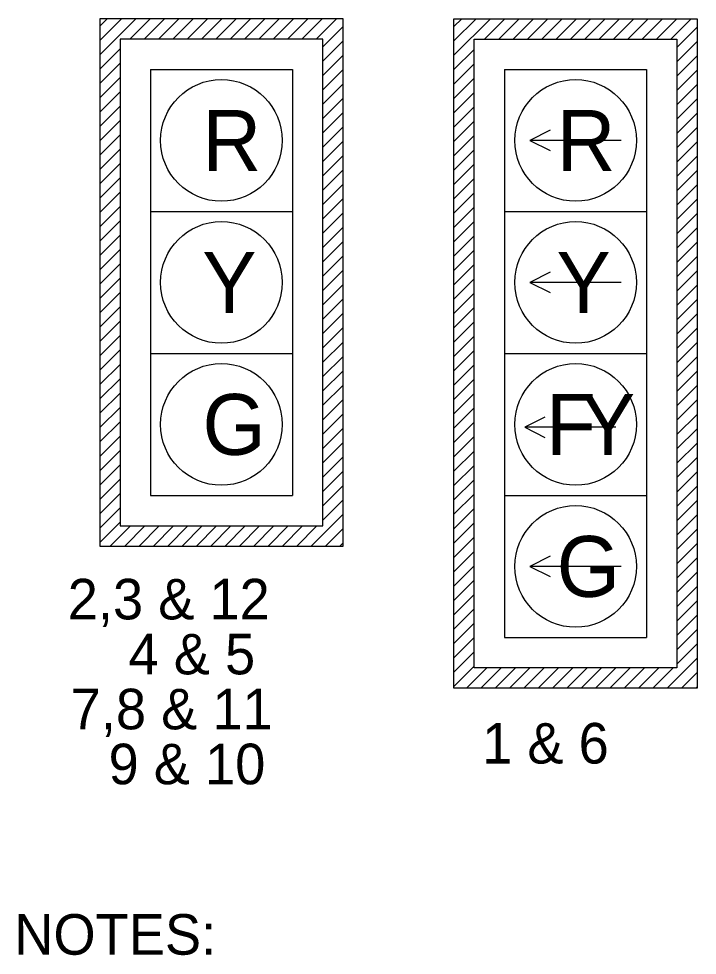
# Model space of a CAD drawing. Extents: x 1281646 to 1282646, y 1891886 to 1892526.
# Drawn here: x 1281835.1 to 1281902, y 1891988.1 to 1892080.4 of the extents above; entities that cross this region are included whole.
import ezdxf

# ---------------------------------------------------------------- set-up
doc = ezdxf.new("R2010")
doc.units = 0
doc.layers.add('T_Drafting', color=7, linetype='Continuous')
doc.layers.add('T_Notes', color=7, linetype='Continuous')

msp = doc.modelspace()

# ---------------------------------------------------------------- linework, layer by layer
at = {"layer": 'T_Drafting'}
for p, q in [((1281867.087, 1892080.441), (1281843.087, 1892080.441)), ((1281843.087, 1892080.441), (1281843.087, 1892028.441)), ((1281843.087, 1892076.894), (1281846.634, 1892080.441)), ((1281843.087, 1892078.308), (1281845.22, 1892080.441)), ((1281843.087, 1892079.723), (1281843.806, 1892080.441)), ((1281846.048, 1892078.441), (1281848.048, 1892080.441)), ((1281847.463, 1892078.441), (1281849.463, 1892080.441)), ((1281848.877, 1892078.441), (1281850.877, 1892080.441)), ((1281850.291, 1892078.441), (1281852.291, 1892080.441)), ((1281851.705, 1892078.441), (1281853.705, 1892080.441)), ((1281853.119, 1892078.441), (1281855.119, 1892080.441)), ((1281854.534, 1892078.441), (1281856.534, 1892080.441)), ((1281855.948, 1892078.441), (1281857.948, 1892080.441)), ((1281857.362, 1892078.441), (1281859.362, 1892080.441)), ((1281858.776, 1892078.441), (1281860.776, 1892080.441)), ((1281860.191, 1892078.441), (1281862.191, 1892080.441)), ((1281861.605, 1892078.441), (1281863.605, 1892080.441)), ((1281863.019, 1892078.441), (1281865.019, 1892080.441)), ((1281864.433, 1892078.441), (1281866.433, 1892080.441)), ((1281867.087, 1892028.441), (1281867.087, 1892080.441)), ((1281878.025, 1892014.441), (1281878.025, 1892080.441)), ((1281878.025, 1892080.441), (1281902.025, 1892080.441)), ((1281878.025, 1892076.834), (1281881.632, 1892080.441)), ((1281878.025, 1892078.248), (1281880.218, 1892080.441)), ((1281878.025, 1892079.662), (1281878.804, 1892080.441)), ((1281881.047, 1892078.441), (1281883.047, 1892080.441)), ((1281882.461, 1892078.441), (1281884.461, 1892080.441)), ((1281883.875, 1892078.441), (1281885.875, 1892080.441)), ((1281885.289, 1892078.441), (1281887.289, 1892080.441)), ((1281886.703, 1892078.441), (1281888.703, 1892080.441)), ((1281888.118, 1892078.441), (1281890.118, 1892080.441)), ((1281889.532, 1892078.441), (1281891.532, 1892080.441)), ((1281890.946, 1892078.441), (1281892.946, 1892080.441)), ((1281892.36, 1892078.441), (1281894.36, 1892080.441)), ((1281893.774, 1892078.441), (1281895.774, 1892080.441)), ((1281895.189, 1892078.441), (1281897.189, 1892080.441)), ((1281896.603, 1892078.441), (1281898.603, 1892080.441)), ((1281898.017, 1892078.441), (1281900.017, 1892080.441)), ((1281899.431, 1892078.441), (1281901.431, 1892080.441)), ((1281902.025, 1892080.441), (1281902.025, 1892014.441)), ((1281865.087, 1892077.681), (1281867.087, 1892079.681)), ((1281900.025, 1892077.621), (1281902.025, 1892079.621)), ((1281865.087, 1892076.267), (1281867.087, 1892078.267)), ((1281900.025, 1892076.207), (1281902.025, 1892078.207)), ((1281843.087, 1892075.48), (1281845.087, 1892077.48)), ((1281878.025, 1892075.42), (1281880.025, 1892077.42)), ((1281865.087, 1892074.853), (1281867.087, 1892076.853)), ((1281900.025, 1892074.792), (1281902.025, 1892076.792)), ((1281843.087, 1892074.066), (1281845.087, 1892076.066)), ((1281848.087, 1892075.441), (1281862.087, 1892075.441)), ((1281848.087, 1892075.441), (1281848.087, 1892061.441)), ((1281862.087, 1892075.441), (1281862.087, 1892061.441)), ((1281865.087, 1892073.438), (1281867.087, 1892075.438)), ((1281878.025, 1892074.005), (1281880.025, 1892076.005)), ((1281883.025, 1892075.441), (1281897.025, 1892075.441)), ((1281883.025, 1892075.441), (1281883.025, 1892061.441)), ((1281897.025, 1892075.441), (1281897.025, 1892061.441)), ((1281900.025, 1892073.378), (1281902.025, 1892075.378)), ((1281843.087, 1892072.652), (1281845.087, 1892074.652)), ((1281878.025, 1892072.591), (1281880.025, 1892074.591)), ((1281865.087, 1892072.024), (1281867.087, 1892074.024)), ((1281900.025, 1892071.964), (1281902.025, 1892073.964)), ((1281843.087, 1892071.237), (1281845.087, 1892073.237)), ((1281865.087, 1892070.61), (1281867.087, 1892072.61)), ((1281878.025, 1892071.177), (1281880.025, 1892073.177)), ((1281900.025, 1892070.55), (1281902.025, 1892072.55)), ((1281843.087, 1892069.823), (1281845.087, 1892071.823)), ((1281878.025, 1892069.763), (1281880.025, 1892071.763)), ((1281865.087, 1892069.196), (1281867.087, 1892071.196)), ((1281900.025, 1892069.135), (1281902.025, 1892071.135)), ((1281843.087, 1892068.409), (1281845.087, 1892070.409)), ((1281865.087, 1892067.782), (1281867.087, 1892069.782)), ((1281878.025, 1892068.349), (1281880.025, 1892070.349)), ((1281900.025, 1892067.721), (1281902.025, 1892069.721)), ((1281843.087, 1892066.995), (1281845.087, 1892068.995)), ((1281878.025, 1892066.934), (1281880.025, 1892068.934)), ((1281865.087, 1892066.367), (1281867.087, 1892068.367)), ((1281894.525, 1892068.441), (1281885.525, 1892068.441)), ((1281900.025, 1892066.307), (1281902.025, 1892068.307)), ((1281843.087, 1892065.581), (1281845.087, 1892067.581)), ((1281865.087, 1892064.953), (1281867.087, 1892066.953)), ((1281878.025, 1892065.52), (1281880.025, 1892067.52)), ((1281900.025, 1892064.893), (1281902.025, 1892066.893)), ((1281843.087, 1892064.166), (1281845.087, 1892066.166)), ((1281878.025, 1892064.106), (1281880.025, 1892066.106)), ((1281865.087, 1892063.539), (1281867.087, 1892065.539)), ((1281900.025, 1892063.479), (1281902.025, 1892065.479)), ((1281843.087, 1892062.752), (1281845.087, 1892064.752)), ((1281865.087, 1892062.125), (1281867.087, 1892064.125)), ((1281878.025, 1892062.692), (1281880.025, 1892064.692)), ((1281843.087, 1892061.338), (1281845.087, 1892063.338)), ((1281878.025, 1892061.278), (1281880.025, 1892063.278)), ((1281900.025, 1892062.064), (1281902.025, 1892064.064)), ((1281865.087, 1892060.71), (1281867.087, 1892062.71)), ((1281900.025, 1892060.65), (1281902.025, 1892062.65)), ((1281843.087, 1892059.924), (1281845.087, 1892061.924)), ((1281848.087, 1892061.441), (1281862.087, 1892061.441)), ((1281848.087, 1892061.441), (1281848.087, 1892047.441)), ((1281862.087, 1892061.441), (1281862.087, 1892047.441)), ((1281878.025, 1892059.863), (1281880.025, 1892061.863)), ((1281883.025, 1892061.441), (1281897.025, 1892061.441)), ((1281883.025, 1892061.441), (1281883.025, 1892047.441)), ((1281897.025, 1892061.441), (1281897.025, 1892047.441)), ((1281843.087, 1892058.509), (1281845.087, 1892060.509)), ((1281865.087, 1892059.296), (1281867.087, 1892061.296)), ((1281878.025, 1892058.449), (1281880.025, 1892060.449)), ((1281900.025, 1892059.236), (1281902.025, 1892061.236)), ((1281865.087, 1892057.882), (1281867.087, 1892059.882)), ((1281900.025, 1892057.822), (1281902.025, 1892059.822)), ((1281843.087, 1892057.095), (1281845.087, 1892059.095)), ((1281878.025, 1892057.035), (1281880.025, 1892059.035)), ((1281843.087, 1892055.681), (1281845.087, 1892057.681)), ((1281865.087, 1892056.468), (1281867.087, 1892058.468)), ((1281900.025, 1892056.408), (1281902.025, 1892058.408)), ((1281865.087, 1892055.054), (1281867.087, 1892057.054)), ((1281878.025, 1892055.621), (1281880.025, 1892057.621)), ((1281900.025, 1892054.993), (1281902.025, 1892056.993)), ((1281843.087, 1892054.267), (1281845.087, 1892056.267)), ((1281878.025, 1892054.207), (1281880.025, 1892056.207)), ((1281865.087, 1892053.639), (1281867.087, 1892055.639)), ((1281900.025, 1892053.579), (1281902.025, 1892055.579)), ((1281843.087, 1892052.853), (1281845.087, 1892054.853)), ((1281865.087, 1892052.225), (1281867.087, 1892054.225)), ((1281878.025, 1892052.792), (1281880.025, 1892054.792)), ((1281894.525, 1892054.441), (1281885.525, 1892054.441)), ((1281900.025, 1892052.165), (1281902.025, 1892054.165)), ((1281843.087, 1892051.438), (1281845.087, 1892053.438)), ((1281878.025, 1892051.378), (1281880.025, 1892053.378)), ((1281865.087, 1892050.811), (1281867.087, 1892052.811)), ((1281900.025, 1892050.751), (1281902.025, 1892052.751)), ((1281843.087, 1892050.024), (1281845.087, 1892052.024)), ((1281865.087, 1892049.397), (1281867.087, 1892051.397)), ((1281878.025, 1892049.964), (1281880.025, 1892051.964)), ((1281900.025, 1892049.336), (1281902.025, 1892051.336)), ((1281843.087, 1892048.61), (1281845.087, 1892050.61)), ((1281878.025, 1892048.55), (1281880.025, 1892050.55)), ((1281865.087, 1892047.983), (1281867.087, 1892049.983)), ((1281900.025, 1892047.922), (1281902.025, 1892049.922)), ((1281843.087, 1892047.196), (1281845.087, 1892049.196)), ((1281865.087, 1892046.568), (1281867.087, 1892048.568)), ((1281878.025, 1892047.135), (1281880.025, 1892049.135)), ((1281900.025, 1892046.508), (1281902.025, 1892048.508)), ((1281843.087, 1892045.782), (1281845.087, 1892047.782)), ((1281878.025, 1892045.721), (1281880.025, 1892047.721)), ((1281848.087, 1892047.441), (1281862.087, 1892047.441)), ((1281848.087, 1892047.441), (1281848.087, 1892033.441)), ((1281862.087, 1892047.441), (1281862.087, 1892033.441)), ((1281865.087, 1892045.154), (1281867.087, 1892047.154)), ((1281883.025, 1892047.441), (1281897.025, 1892047.441)), ((1281883.025, 1892047.441), (1281883.025, 1892033.441)), ((1281897.025, 1892047.441), (1281897.025, 1892033.441)), ((1281900.025, 1892045.094), (1281902.025, 1892047.094)), ((1281843.087, 1892044.367), (1281845.087, 1892046.367)), ((1281865.087, 1892043.74), (1281867.087, 1892045.74)), ((1281878.025, 1892044.307), (1281880.025, 1892046.307)), ((1281900.025, 1892043.68), (1281902.025, 1892045.68)), ((1281843.087, 1892042.953), (1281845.087, 1892044.953)), ((1281878.025, 1892042.893), (1281880.025, 1892044.893)), ((1281865.087, 1892042.326), (1281867.087, 1892044.326)), ((1281900.025, 1892042.265), (1281902.025, 1892044.265)), ((1281843.087, 1892041.539), (1281845.087, 1892043.539)), ((1281865.087, 1892040.911), (1281867.087, 1892042.911)), ((1281878.025, 1892041.479), (1281880.025, 1892043.479)), ((1281843.087, 1892040.125), (1281845.087, 1892042.125)), ((1281878.025, 1892040.064), (1281880.025, 1892042.064)), ((1281900.025, 1892040.851), (1281902.025, 1892042.851)), ((1281865.087, 1892039.497), (1281867.087, 1892041.497)), ((1281900.025, 1892039.437), (1281902.025, 1892041.437)), ((1281843.087, 1892038.71), (1281845.087, 1892040.71)), ((1281878.025, 1892038.65), (1281880.025, 1892040.65)), ((1281894, 1892040.164), (1281885, 1892040.164)), ((1281843.087, 1892037.296), (1281845.087, 1892039.296)), ((1281865.087, 1892038.083), (1281867.087, 1892040.083)), ((1281878.025, 1892037.236), (1281880.025, 1892039.236)), ((1281900.025, 1892038.023), (1281902.025, 1892040.023)), ((1281865.087, 1892036.669), (1281867.087, 1892038.669)), ((1281900.025, 1892036.609), (1281902.025, 1892038.609)), ((1281843.087, 1892035.882), (1281845.087, 1892037.882)), ((1281878.025, 1892035.822), (1281880.025, 1892037.822)), ((1281843.087, 1892034.468), (1281845.087, 1892036.468)), ((1281865.087, 1892035.255), (1281867.087, 1892037.255)), ((1281878.025, 1892034.408), (1281880.025, 1892036.408)), ((1281900.025, 1892035.194), (1281902.025, 1892037.194)), ((1281865.087, 1892033.84), (1281867.087, 1892035.84)), ((1281900.025, 1892033.78), (1281902.025, 1892035.78)), ((1281843.087, 1892033.054), (1281845.087, 1892035.054)), ((1281878.025, 1892032.993), (1281880.025, 1892034.993)), ((1281843.087, 1892031.639), (1281845.087, 1892033.639)), ((1281865.087, 1892032.426), (1281867.087, 1892034.426)), ((1281900.025, 1892032.366), (1281902.025, 1892034.366)), ((1281848.087, 1892033.441), (1281862.087, 1892033.441)), ((1281865.087, 1892031.012), (1281867.087, 1892033.012)), ((1281878.025, 1892031.579), (1281880.025, 1892033.579)), ((1281883.025, 1892033.441), (1281897.025, 1892033.441)), ((1281883.025, 1892033.441), (1281883.025, 1892019.441)), ((1281897.025, 1892033.441), (1281897.025, 1892019.441)), ((1281900.025, 1892030.952), (1281902.025, 1892032.952)), ((1281843.087, 1892030.225), (1281845.087, 1892032.225)), ((1281878.025, 1892030.165), (1281880.025, 1892032.165)), ((1281863.931, 1892028.441), (1281867.087, 1892031.598)), ((1281900.025, 1892029.537), (1281902.025, 1892031.537)), ((1281843.087, 1892028.811), (1281845.087, 1892030.811)), ((1281844.132, 1892028.441), (1281846.132, 1892030.441)), ((1281845.546, 1892028.441), (1281847.546, 1892030.441)), ((1281846.96, 1892028.441), (1281848.96, 1892030.441)), ((1281848.374, 1892028.441), (1281850.374, 1892030.441)), ((1281849.789, 1892028.441), (1281851.789, 1892030.441)), ((1281851.203, 1892028.441), (1281853.203, 1892030.441)), ((1281852.617, 1892028.441), (1281854.617, 1892030.441)), ((1281854.031, 1892028.441), (1281856.031, 1892030.441)), ((1281855.445, 1892028.441), (1281857.445, 1892030.441)), ((1281856.86, 1892028.441), (1281858.86, 1892030.441)), ((1281858.274, 1892028.441), (1281860.274, 1892030.441)), ((1281859.688, 1892028.441), (1281861.688, 1892030.441)), ((1281861.102, 1892028.441), (1281863.102, 1892030.441)), ((1281862.516, 1892028.441), (1281864.516, 1892030.441)), ((1281865.345, 1892028.441), (1281867.087, 1892030.184)), ((1281878.025, 1892028.751), (1281880.025, 1892030.751)), ((1281900.025, 1892028.123), (1281902.025, 1892030.123)), ((1281878.025, 1892027.336), (1281880.025, 1892029.336)), ((1281843.087, 1892028.441), (1281867.087, 1892028.441)), ((1281866.759, 1892028.441), (1281867.087, 1892028.769)), ((1281900.025, 1892026.709), (1281902.025, 1892028.709)), ((1281878.025, 1892025.922), (1281880.025, 1892027.922)), ((1281900.025, 1892025.295), (1281902.025, 1892027.295)), ((1281878.025, 1892024.508), (1281880.025, 1892026.508)), ((1281894.525, 1892026.441), (1281885.525, 1892026.441)), ((1281900.025, 1892023.881), (1281902.025, 1892025.881)), ((1281878.025, 1892023.094), (1281880.025, 1892025.094)), ((1281900.025, 1892022.466), (1281902.025, 1892024.466)), ((1281878.025, 1892021.68), (1281880.025, 1892023.68)), ((1281900.025, 1892021.052), (1281902.025, 1892023.052)), ((1281878.025, 1892020.265), (1281880.025, 1892022.265)), ((1281900.025, 1892019.638), (1281902.025, 1892021.638)), ((1281878.025, 1892018.851), (1281880.025, 1892020.851)), ((1281900.025, 1892018.224), (1281902.025, 1892020.224)), ((1281878.025, 1892017.437), (1281880.025, 1892019.437)), ((1281883.025, 1892019.441), (1281897.025, 1892019.441)), ((1281878.025, 1892016.023), (1281880.025, 1892018.023)), ((1281900.025, 1892016.81), (1281902.025, 1892018.81)), ((1281899.071, 1892014.441), (1281902.025, 1892017.395)), ((1281878.025, 1892014.609), (1281880.025, 1892016.609)), ((1281879.272, 1892014.441), (1281881.272, 1892016.441)), ((1281880.686, 1892014.441), (1281882.686, 1892016.441)), ((1281882.1, 1892014.441), (1281884.1, 1892016.441)), ((1281883.515, 1892014.441), (1281885.515, 1892016.441)), ((1281884.929, 1892014.441), (1281886.929, 1892016.441)), ((1281886.343, 1892014.441), (1281888.343, 1892016.441)), ((1281887.757, 1892014.441), (1281889.757, 1892016.441)), ((1281889.171, 1892014.441), (1281891.171, 1892016.441)), ((1281890.586, 1892014.441), (1281892.586, 1892016.441)), ((1281892, 1892014.441), (1281894, 1892016.441)), ((1281893.414, 1892014.441), (1281895.414, 1892016.441)), ((1281894.828, 1892014.441), (1281896.828, 1892016.441)), ((1281896.243, 1892014.441), (1281898.243, 1892016.441)), ((1281897.657, 1892014.441), (1281899.657, 1892016.441)), ((1281900.485, 1892014.441), (1281902.025, 1892015.981)), ((1281902.025, 1892014.441), (1281878.025, 1892014.441)), ((1281901.899, 1892014.441), (1281902.025, 1892014.567))]:
    msp.add_line(p, q, dxfattribs=at)
for points in [[(1281865.087, 1892030.441), (1281865.087, 1892078.441), (1281845.087, 1892078.441), (1281845.087, 1892030.441)], [(1281880.025, 1892016.441), (1281880.025, 1892078.441), (1281900.025, 1892078.441), (1281900.025, 1892016.441)]]:
    msp.add_lwpolyline(points, close=True, dxfattribs=at)
for points in [[(1281887.525, 1892069.441), (1281885.525, 1892068.441), (1281887.525, 1892067.441)], [(1281887.525, 1892055.441), (1281885.525, 1892054.441), (1281887.525, 1892053.441)], [(1281887, 1892041.164), (1281885, 1892040.164), (1281887, 1892039.164)], [(1281887.525, 1892027.441), (1281885.525, 1892026.441), (1281887.525, 1892025.441)]]:
    msp.add_lwpolyline(points, dxfattribs=at)
for centre in [(1281855.087, 1892068.441), (1281890.025, 1892068.441), (1281855.087, 1892054.441), (1281890.025, 1892054.441), (1281855.087, 1892040.441), (1281890.025, 1892040.441), (1281890.025, 1892026.441)]:
    msp.add_circle(centre, 6, dxfattribs=at)

# ---------------------------------------------------------------- texts
for s, p in [('R', (1281853.222, 1892065.442)), ('R', (1281888.16, 1892065.442)), ('Y', (1281853.198, 1892051.442)), ('Y', (1281888.136, 1892051.442)), ('G', (1281853.221, 1892037.442)), ('F', (1281887.12, 1892037.442)), ('Y', (1281890.545, 1892037.442)), ('G', (1281888.159, 1892023.442))]:
    msp.add_text(s, height=5.998, dxfattribs=at).set_placement(p)
at = {"layer": 'T_Notes'}
for s, p in [('2,3 & 12', (1281839.931, 1892021.22)), ('4 & 5', (1281845.931, 1892015.801)), ('7,8 & 11', (1281840.223, 1892010.383)), ('1 & 6', (1281880.806, 1892007.007)), ('9 & 10', (1281843.958, 1892004.965)), ('NOTES:', (1281834.657, 1891988.162))]:
    msp.add_text(s, height=4, dxfattribs=at).set_placement(p)

doc.saveas('drawing.dxf')
